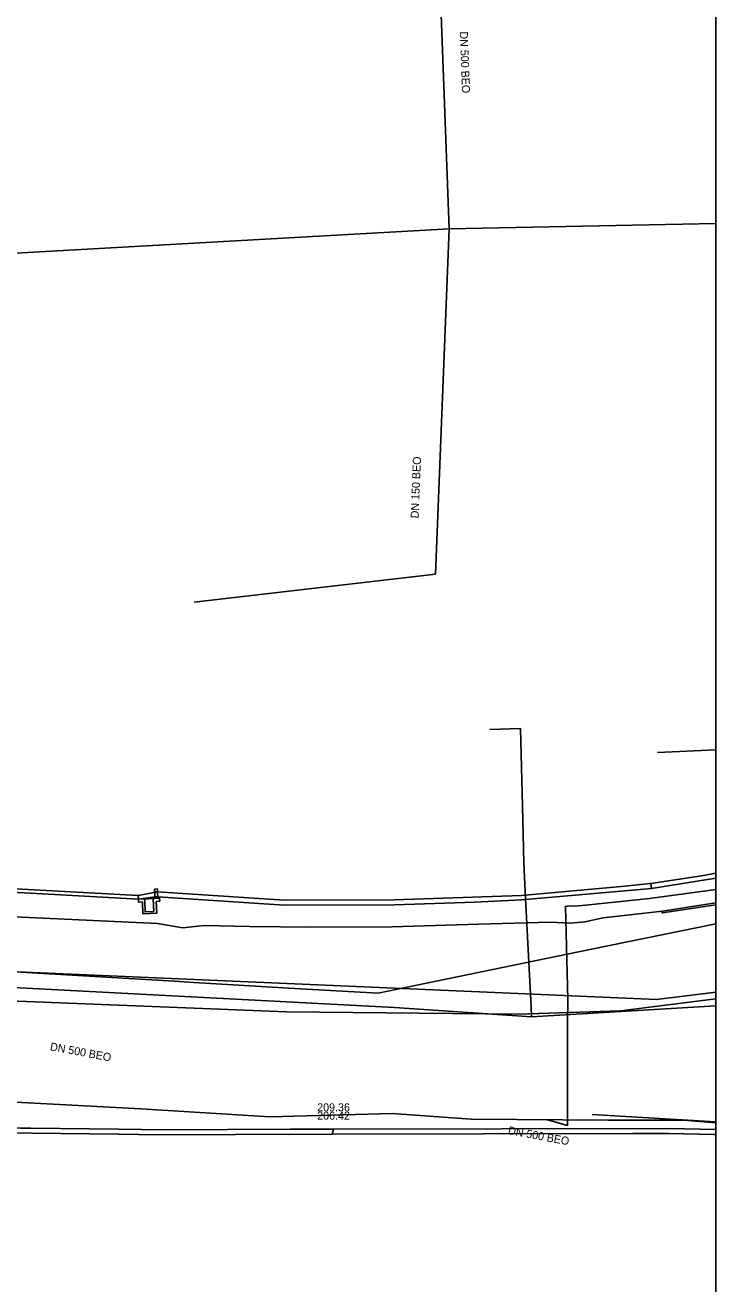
# Model space of a CAD drawing. Extents: x -599951 to -598963, y -1164095 to -1162939.
# Drawn here: x -599032.2 to -598963.2, y -1163195.6 to -1163069.8 of the extents above; entities that cross this region are included whole.
import ezdxf

# ---------------------------------------------------------------- set-up
doc = ezdxf.new("R2010")
doc.units = 0
for name, color, linetype in [('Level 3', 7, 'Continuous'), ('Vrstva 1', 7, 'Continuous'), ('Vrstva 12', 7, 'Continuous'), ('Vrstva 13', 7, 'Continuous'), ('Vrstva 19', 7, 'Continuous'), ('Vrstva 3', 7, 'Continuous'), ('Vrstva 32', 7, 'Continuous'), ('Vrstva 42', 7, 'Continuous'), ('Vrstva 53', 7, 'Continuous'), ('Vrstva 55', 7, 'Continuous'), ('Vrstva 9', 7, 'Continuous')]:
    doc.layers.add(name, color=color, linetype=linetype)

msp = doc.modelspace()

# ---------------------------------------------------------------- linework, layer by layer
at = {"layer": 'Level 3'}
for points in [[(-599052.37, -1163155.12), (-599039.31, -1163155.81), (-599020.94, -1163156.83), (-599020.92, -1163157.17), (-599041.95, -1163156), (-599054.16, -1163155.35), (-599107.63, -1163152.5), (-599131.92, -1163151.18), (-599132.08, -1163151.18), (-599132.06, -1163150.86), (-599126.99, -1163151.13), (-599126.38, -1163151.17), (-599106.06, -1163152.26), (-599082.99, -1163153.48), (-599062.21, -1163154.63)], [(-599020.94, -1163156.83), (-599019, -1163156.45), (-599006.34, -1163157.29), (-598995.37, -1163157.24), (-598982.62, -1163156.821), (-598972.661, -1163155.924), (-598969.71, -1163155.61), (-598969.645, -1163156.108), (-598982.611, -1163157.257), (-598987.285, -1163157.476), (-598995.34, -1163157.74), (-599006.36, -1163157.79), (-599018.98, -1163156.95), (-599019.28, -1163156.94), (-599020.92, -1163157.17)], [(-599019.32, -1163156.18), (-599019.02, -1163156.16), (-599019, -1163156.45), (-599018.98, -1163157.09), (-599019.27, -1163157.11), (-599019.28, -1163156.94)], [(-599019.32, -1163156.18), (-599019.02, -1163156.16), (-599019, -1163156.45), (-599018.98, -1163157.09), (-599019.27, -1163157.11), (-599019.28, -1163156.94)], [(-599020.28, -1163157.46), (-599020.24, -1163158.45), (-599019.38, -1163158.4), (-599019.45, -1163157.12), (-599018.81, -1163157.08), (-599018.79, -1163157.38), (-599019.13, -1163157.4), (-599019.07, -1163158.58), (-599020.46, -1163158.65), (-599020.51, -1163157.46), (-599020.9, -1163157.47), (-599020.91, -1163157.16), (-599020.29, -1163157.17)], [(-599020.28, -1163157.46), (-599020.24, -1163158.45), (-599019.38, -1163158.4), (-599019.45, -1163157.12), (-599018.81, -1163157.08), (-599018.79, -1163157.38), (-599019.13, -1163157.4), (-599019.07, -1163158.58), (-599020.46, -1163158.65), (-599020.51, -1163157.46), (-599020.9, -1163157.47), (-599020.91, -1163157.16), (-599020.29, -1163157.17)], [(-599019.45, -1163157.12), (-599019.27, -1163157.11), (-599018.81, -1163157.08), (-599018.79, -1163157.38), (-599019.13, -1163157.4), (-599019.07, -1163158.58), (-599020.46, -1163158.65), (-599020.51, -1163157.46), (-599020.9, -1163157.47), (-599020.91, -1163157.16), (-599020.29, -1163157.17)], [(-599040.2, -1163180.49), (-599052.09, -1163180.24), (-599052.06, -1163179.74), (-599048.48, -1163179.82), (-599047.48, -1163179.84), (-599046.47, -1163179.86), (-599045.47, -1163179.88), (-599040.32, -1163179.99), (-599034.67, -1163180.05), (-599033.66, -1163180.06), (-599032.66, -1163180.08), (-599031.66, -1163180.09), (-599022.91, -1163180.19), (-599018.291, -1163180.243), (-599005.759, -1163180.193), (-599001.409, -1163180.17), (-599001.555, -1163180.67), (-599011.198, -1163180.719), (-599018.832, -1163180.744), (-599022.91, -1163180.69)]]:
    msp.add_lwpolyline(points, close=True, dxfattribs=at)
for points in [[(-599019, -1163156.45), (-599019.3, -1163156.44)], [(-599019, -1163156.45), (-599019.3, -1163156.44)], [(-599018.98, -1163156.95), (-599019.28, -1163156.94)], [(-599018.98, -1163156.95), (-599019.28, -1163156.94)]]:
    msp.add_lwpolyline(points, dxfattribs=at)
at = {"layer": 'Vrstva 1'}
for points in [[(-598996.97, -1163166.59), (-598990.201, -1163165.195), (-598975.637, -1163162.193), (-598963.215, -1163159.633)], [(-599041.79, -1163163.95), (-599017.301, -1163165.392), (-599015.385, -1163165.505), (-599005.332, -1163166.097), (-598996.97, -1163166.59)]]:
    msp.add_lwpolyline(points, dxfattribs=at)
at = {"layer": 'Vrstva 13'}
msp.add_lwpolyline([(-598963.215, -1163166.478), (-598969.13, -1163167.22), (-599128.488, -1163160.328)], dxfattribs=at)
at = {"layer": 'Vrstva 19'}
for points in [[(-598981.62, -1163168.95), (-598981.67, -1163167.95), (-598982.19, -1163157.76), (-598982.4, -1163153.58), (-598982.54, -1163147.84), (-598982.73, -1163140.12), (-598985.81, -1163140.2)], [(-598963.215, -1163167.844), (-598981.62, -1163168.95), (-598995.32, -1163168.02), (-599126.72, -1163161.13)]]:
    msp.add_lwpolyline(points, dxfattribs=at)
at = {"layer": 'Vrstva 3'}
for points in [[(-598963.215, -1163155.084), (-598963.215, -1163154.591), (-598964.64, -1163154.85), (-598969.71, -1163155.61), (-598969.645, -1163156.108)], [(-598963.215, -1163180.715), (-598963.215, -1163180.215), (-598967.889, -1163180.101), (-599001.409, -1163180.17), (-599001.555, -1163180.67), (-598971.495, -1163180.613), (-598967.87, -1163180.6), (-598963.4, -1163180.71)]]:
    msp.add_lwpolyline(points, close=True, dxfattribs=at)
at = {"layer": 'Vrstva 32'}
for p, q in [((-598963.215, -1163157.551), (-598968.55, -1163158.38)), ((-598968.53, -1163158.56), (-598963.215, -1163157.742))]:
    msp.add_line(p, q, dxfattribs=at)
msp.add_lwpolyline([(-598968.55, -1163158.38), (-598974.47, -1163159.05), (-598976.3, -1163159.46), (-598977.72, -1163159.58), (-598979.76, -1163159.47), (-598986.92, -1163159.68), (-598995.57, -1163159.95), (-599003.62, -1163159.98), (-599009.81, -1163159.9), (-599014.3, -1163159.81), (-599015.56, -1163159.94), (-599016.47, -1163160.06), (-599019, -1163159.63), (-599031.87, -1163159.01), (-599046.86, -1163158.25)], dxfattribs=at)
msp.add_arc((-598968.54, -1163158.47), 0.0906, 96.34244, 281.16986, dxfattribs=at)
at = {"layer": 'Vrstva 42'}
for points in [[(-598976.25, -1163157.78), (-598969.83, -1163157.11), (-598963.215, -1163156.209)], [(-598980.04, -1163179.25), (-598978.04, -1163179.8), (-598978.02, -1163169.66), (-598978, -1163167.22), (-598978.24, -1163157.91), (-598977.84, -1163157.85), (-598977.36, -1163157.89), (-598976.25, -1163157.78)], [(-599035.09, -1163177.39), (-599020.68, -1163178.14), (-599007.77, -1163178.94), (-598995.55, -1163178.62), (-598987.67, -1163179.19), (-598973.96, -1163179.29), (-598966.43, -1163179.29), (-598963.215, -1163179.531)], [(-599035.09, -1163177.39), (-599020.68, -1163178.14), (-599007.77, -1163178.94), (-598995.55, -1163178.62), (-598987.67, -1163179.19), (-598973.96, -1163179.29), (-598966.43, -1163179.29), (-598963.215, -1163179.531)]]:
    msp.add_lwpolyline(points, dxfattribs=at)
at = {"layer": 'Vrstva 53'}
msp.add_lwpolyline([(-599951.125, -1164094.695), (-598963.215, -1164094.695), (-598963.215, -1162939.4), (-599951.125, -1162939.4)], close=True, dxfattribs=at)
at = {"layer": 'Vrstva 55'}
msp.add_line((-598963.215, -1163179.462), (-598975.58, -1163178.72), dxfattribs=at)
msp.add_lwpolyline([(-598963.215, -1163167.135), (-598972.75, -1163168.34), (-598982.93, -1163168.67), (-599006.1, -1163168.45), (-599034.63, -1163167.33), (-599088.67, -1163164.42), (-599124.376, -1163162.481), (-599128.207, -1163162.273)], dxfattribs=at)
at = {"layer": 'Vrstva 9'}
for p, q in [((-598990.802, -1163065.146), (-598989.864, -1163090.159)), ((-598989.864, -1163090.159), (-598963.215, -1163089.632)), ((-598969.057, -1163142.506), (-598963.215, -1163142.262))]:
    msp.add_line(p, q, dxfattribs=at)
for points in [[(-599090.294, -1163095.746), (-599074.642, -1163094.962), (-599053.936, -1163093.751), (-598989.864, -1163090.159)], [(-599015.334, -1163127.492), (-598991.242, -1163124.681), (-598989.864, -1163090.159)]]:
    msp.add_lwpolyline(points, dxfattribs=at)

# ---------------------------------------------------------------- texts
at = {"layer": 'Vrstva 12'}
for s, rotation, p in [('DN 500 BEO', 272.14728, (-598988.799, -1163070.423)), ('DN 150 BEO', 87.71388, (-598992.918, -1163119.114)), ('DN 500 BEO', 349.44696, (-599029.791, -1163172.278)), ('DN 500 BEO', 349.61885, (-598984.019, -1163180.675))]:
    msp.add_text(s, height=0.8, rotation=rotation, dxfattribs=at).set_placement(p)
for s, p in [('209.36', (-599003.052, -1163178.398)), ('206.42', (-599003.052, -1163179.23))]:
    msp.add_text(s, height=0.8, dxfattribs=at).set_placement(p)

doc.saveas('drawing.dxf')
